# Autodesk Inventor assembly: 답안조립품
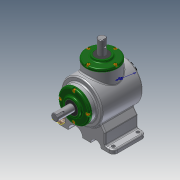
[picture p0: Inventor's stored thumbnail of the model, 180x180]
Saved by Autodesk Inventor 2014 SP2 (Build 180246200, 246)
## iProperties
Created: 2018-08
Part Number: 답안조립품
Document SubType Name: Assembly
Designer: 거성
Author: 거성
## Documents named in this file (14)
- C:\Users\거성\Desktop\480808V1019\답안조립품.iam
- C:\Users\거성\Desktop\480808V1019\본체.ipt
- C:\Users\거성\Desktop\480808V1019\메인 축.ipt
- 메인 축.ipt
- C:\Users\거성\Desktop\480808V1019\베어링 6203.ipt
- C:\Users\거성\Desktop\480808V1019\오일실 17 32 8.ipt
- C:\Users\거성\Desktop\480808V1019\커버.ipt
- C:\Users\거성\Desktop\480808V1019\메인 베벨기어.ipt
- C:\Users\거성\Desktop\480808V1019\키 5x5.ipt
- C:\Users\거성\Desktop\480808V1019\서브 베벨기어.ipt
- C:\Users\거성\Desktop\480808V1019\서브 축.ipt
- 서브 축.ipt
- C:\Users\거성\Desktop\480808V1019\키 4x4.ipt
- C:\Users\거성\Desktop\480808V1019\볼트 M4.ipt
